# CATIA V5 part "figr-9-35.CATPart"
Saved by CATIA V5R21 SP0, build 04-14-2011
Part number: Part1
Bounding box of the stored display mesh (mm): x -250 to 0, y -60 to 60, z 0 to 100
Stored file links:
  D:\CATIA V5R21 E-RESOURCES\CATIA-V5R21\catia-v5r21-prt\c09-catia-v5r20-prt\c09-catia-v5r21-figr-9-35.CATPart
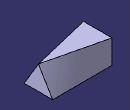
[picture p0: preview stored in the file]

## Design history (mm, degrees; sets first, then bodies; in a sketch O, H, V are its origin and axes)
Body1 (main body)
  Sketch1 on yz-plane, origin (0, 0, 0), H (0, 1, 0), V (0, 0, 1)
    point P1 (-60, 0)
    line L1 (-60, 0) -> (0, 100)
    point P2 (0, 100)
    line L2 (0, 100) -> (60, 0)
    point P3 (60, 0)
    line L3 (60, 0) -> (-60, 0)
    coincidence: P1 H, P2 V, P3 H
    horizontal: L3 H
    midpoint: O L3
  Sketch2, origin (-250, 0, 0), H (0, 1, 0), V (0, 0, 1)
    point P1 (-60, 0)
    line L1 (-60, 0) -> (60, 0)
    line L2 (60, 0) -> (60, 100)
    line L3 (60, 100) -> (-60, 100)
    line L4 (-60, 100) -> (-60, 0)
    coincidence: P1 H
    horizontal: L1 H, L3 H
    vertical: L2 V, L4 V
  Loft1: Sections (Sketch1; Sketch2), SectionCouplingPoints ({coupling CouplingPoints (vertex [element of Sketch1 | element of Sketch1]; vertex [element of Sketch2 | element of Sketch2])}; {coupling CouplingPoints (vertex [element of Sketch1 | element of Sketch1]; vertex [element of Sketch2 | element of Sketch2])}; {coupling CouplingPoints (vertex [element of Sketch1 | element of Sketch1]; vertex [element of Sketch2 | element of Sketch2])})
